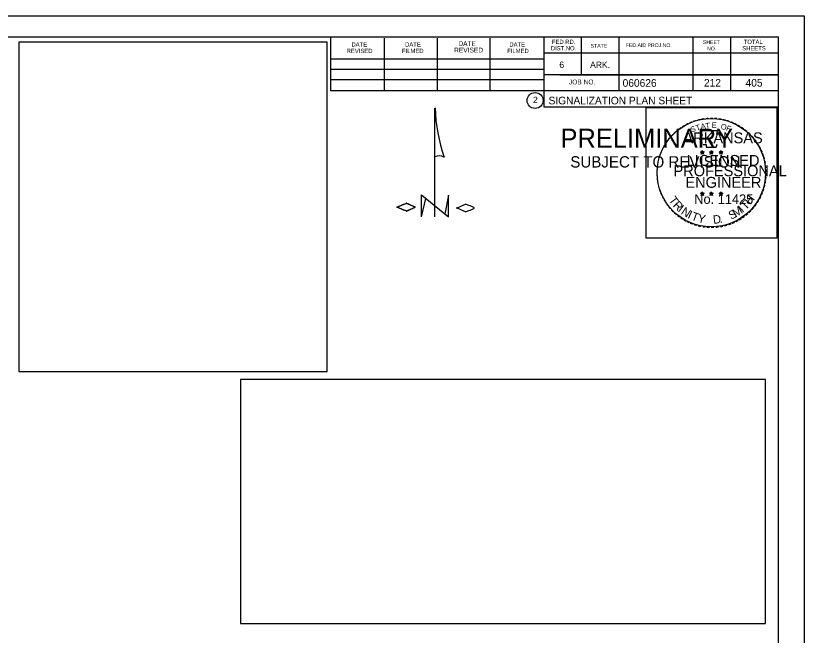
# Model space of a CAD drawing. Extents: x 1280742 to 1281742, y 1892348 to 1892988.
# Drawn here: x 1281307.2 to 1281741.9, y 1892646.8 to 1892988 of the extents above; entities that cross this region are included whole.
import ezdxf

# ---------------------------------------------------------------- set-up
doc = ezdxf.new("R2010")
doc.units = 0
for name, color, linetype in [('R_Border', 7, 'Continuous'), ('R_Border PE', 7, 'Continuous'), ('R_Border Prem', 7, 'Continuous'), ('R_No Plot', 7, 'Continuous'), ('T_Drafting', 7, 'Continuous')]:
    doc.layers.add(name, color=color, linetype=linetype)

msp = doc.modelspace()

# ---------------------------------------------------------------- linework, layer by layer
at = {"layer": 'R_Border'}
for p, q in [((1280779.11, 1892976.34), (1281727.65, 1892976.34)), ((1281480.87, 1892946.7), (1281480.87, 1892976.34)), ((1281510.45, 1892946.7), (1281510.45, 1892975.74)), ((1281539.73, 1892946.7), (1281539.73, 1892975.74)), ((1281568.77, 1892946.7), (1281568.77, 1892975.74)), ((1281598.35, 1892976.34), (1281598.35, 1892937.94)), ((1281618.87, 1892976.34), (1281618.87, 1892955.52)), ((1281639.69, 1892976.34), (1281639.69, 1892946.7)), ((1281680.43, 1892976.34), (1281680.43, 1892946.7)), ((1281701.25, 1892976.34), (1281701.25, 1892946.7)), ((1281727.65, 1892359.96), (1281727.65, 1892976.34)), ((1281480.87, 1892964.28), (1281598.35, 1892964.28)), ((1281727.65, 1892967.52), (1281598.35, 1892967.52)), ((1281727.65, 1892967.58), (1281727.65, 1892967.58)), ((1281480.87, 1892958.7), (1281598.35, 1892958.7)), ((1281727.65, 1892955.52), (1281598.35, 1892955.52)), ((1281607.23, 1892955.52), (1281727.65, 1892955.52)), ((1281480.87, 1892946.7), (1281480.87, 1892952.88)), ((1281480.87, 1892952.88), (1281598.35, 1892952.88)), ((1281727.65, 1892946.7), (1281480.87, 1892946.7)), ((1281598.35, 1892937.94), (1281727.65, 1892937.94))]:
    msp.add_line(p, q, dxfattribs=at)
msp.add_circle((1281593.51, 1892941.35), 4.4, dxfattribs=at)
at = {"layer": 'R_Border PE'}
for p, q in [((1281684.63, 1892913.02), (1281685.68, 1892912.69)), ((1281684.63, 1892913.02), (1281685.39, 1892912.89)), ((1281684.63, 1892913.02), (1281685.34, 1892912.66)), ((1281685.03, 1892911.8), (1281685.68, 1892912.69)), ((1281685.03, 1892911.8), (1281685.41, 1892912.53)), ((1281685.03, 1892911.8), (1281685.67, 1892912.45)), ((1281685.68, 1892913.78), (1281685.55, 1892913.03)), ((1281686.31, 1892911.8), (1281685.67, 1892912.44)), ((1281685.68, 1892912.69), (1281685.68, 1892913.78)), ((1281685.68, 1892913.78), (1281685.82, 1892913.03)), ((1281686.72, 1892913.02), (1281685.68, 1892912.69)), ((1281686.31, 1892911.8), (1281685.68, 1892912.69)), ((1281686.72, 1892913.02), (1281685.86, 1892912.87)), ((1281686.31, 1892911.8), (1281685.9, 1892912.67)), ((1281686.72, 1892913.02), (1281686.1, 1892912.72)), ((1281689.64, 1892913.02), (1281690.69, 1892912.69)), ((1281689.64, 1892913.02), (1281690.4, 1892912.89)), ((1281689.64, 1892913.02), (1281690.35, 1892912.66)), ((1281690.04, 1892911.8), (1281690.69, 1892912.69)), ((1281690.04, 1892911.8), (1281690.42, 1892912.53)), ((1281690.04, 1892911.8), (1281690.68, 1892912.45)), ((1281690.69, 1892913.78), (1281690.56, 1892913.03)), ((1281691.32, 1892911.8), (1281690.68, 1892912.44)), ((1281690.69, 1892912.69), (1281690.69, 1892913.78)), ((1281690.69, 1892913.78), (1281690.83, 1892913.03)), ((1281691.73, 1892913.02), (1281690.69, 1892912.69)), ((1281691.32, 1892911.8), (1281690.69, 1892912.69)), ((1281691.73, 1892913.02), (1281690.87, 1892912.87)), ((1281691.32, 1892911.8), (1281690.91, 1892912.67)), ((1281691.73, 1892913.02), (1281691.11, 1892912.72)), ((1281694.93, 1892912.99), (1281695.98, 1892912.65)), ((1281694.93, 1892912.99), (1281695.69, 1892912.85)), ((1281694.93, 1892912.99), (1281695.64, 1892912.62)), ((1281695.33, 1892911.76), (1281695.98, 1892912.65)), ((1281695.33, 1892911.76), (1281695.71, 1892912.49)), ((1281695.33, 1892911.76), (1281695.97, 1892912.41)), ((1281695.98, 1892913.75), (1281695.85, 1892912.99)), ((1281696.62, 1892911.76), (1281695.97, 1892912.4)), ((1281695.98, 1892912.65), (1281695.98, 1892913.75)), ((1281695.98, 1892913.75), (1281696.12, 1892913)), ((1281697.02, 1892912.99), (1281695.98, 1892912.65)), ((1281696.62, 1892911.76), (1281695.98, 1892912.65)), ((1281697.02, 1892912.99), (1281696.16, 1892912.84)), ((1281696.62, 1892911.76), (1281696.21, 1892912.63)), ((1281697.02, 1892912.99), (1281696.41, 1892912.68)), ((1281684.62, 1892890.3), (1281685.66, 1892889.97)), ((1281684.62, 1892890.3), (1281685.38, 1892890.17)), ((1281684.62, 1892890.3), (1281685.33, 1892889.94)), ((1281685.66, 1892891.06), (1281685.54, 1892890.31)), ((1281685.66, 1892889.97), (1281685.66, 1892891.06)), ((1281685.66, 1892891.06), (1281685.81, 1892890.31)), ((1281686.7, 1892890.3), (1281685.66, 1892889.97)), ((1281686.7, 1892890.3), (1281685.85, 1892890.16)), ((1281686.7, 1892890.3), (1281686.09, 1892890)), ((1281689.62, 1892890.3), (1281690.67, 1892889.97)), ((1281689.62, 1892890.3), (1281690.38, 1892890.17)), ((1281689.62, 1892890.3), (1281690.33, 1892889.94)), ((1281690.67, 1892891.06), (1281690.55, 1892890.31)), ((1281690.67, 1892889.97), (1281690.67, 1892891.06)), ((1281690.67, 1892891.06), (1281690.82, 1892890.31)), ((1281691.71, 1892890.3), (1281690.67, 1892889.97)), ((1281691.71, 1892890.3), (1281690.85, 1892890.16)), ((1281691.71, 1892890.3), (1281691.1, 1892890)), ((1281695.97, 1892891.03), (1281695.85, 1892890.28)), ((1281695.97, 1892889.94), (1281695.97, 1892891.03)), ((1281695.97, 1892891.03), (1281696.12, 1892890.28)), ((1281685.02, 1892889.08), (1281685.66, 1892889.97)), ((1281685.02, 1892889.08), (1281685.39, 1892889.81)), ((1281685.02, 1892889.08), (1281685.66, 1892889.73)), ((1281686.3, 1892889.08), (1281685.66, 1892889.97)), ((1281686.3, 1892889.08), (1281685.66, 1892889.72)), ((1281686.3, 1892889.08), (1281685.89, 1892889.95)), ((1281690.02, 1892889.08), (1281690.67, 1892889.97)), ((1281690.02, 1892889.08), (1281690.4, 1892889.81)), ((1281690.02, 1892889.08), (1281690.66, 1892889.73)), ((1281691.31, 1892889.08), (1281690.66, 1892889.72)), ((1281691.31, 1892889.08), (1281690.67, 1892889.97)), ((1281691.31, 1892889.08), (1281690.9, 1892889.95)), ((1281694.92, 1892890.27), (1281695.97, 1892889.94)), ((1281694.92, 1892890.27), (1281695.68, 1892890.14)), ((1281694.92, 1892890.27), (1281695.64, 1892889.91)), ((1281695.32, 1892889.05), (1281695.97, 1892889.94)), ((1281695.32, 1892889.05), (1281695.7, 1892889.78)), ((1281695.32, 1892889.05), (1281695.97, 1892889.7)), ((1281697.01, 1892890.27), (1281695.97, 1892889.94)), ((1281696.61, 1892889.05), (1281695.97, 1892889.94)), ((1281696.61, 1892889.05), (1281695.97, 1892889.69)), ((1281697.01, 1892890.27), (1281696.15, 1892890.13)), ((1281696.61, 1892889.05), (1281696.2, 1892889.92)), ((1281697.01, 1892890.27), (1281696.4, 1892889.97))]:
    msp.add_line(p, q, dxfattribs=at)
for points in [[(1281684.75, 1892924.66), (1281685.56, 1892922.17)], [(1281695.28, 1892921.89), (1281695.71, 1892922.74), (1281693.66, 1892922.67), (1281694.1, 1892924.66), (1281684.75, 1892924.66)], [(1281686.23, 1892917.39), (1281686.23, 1892917.13), (1281687.92, 1892917.07), (1281687.75, 1892915.65), (1281693.36, 1892915.65), (1281693.97, 1892917.26)], [(1281685.68, 1892913.78), (1281686.31, 1892911.8), (1281684.63, 1892913.02), (1281686.72, 1892913.02), (1281685.03, 1892911.8), (1281685.68, 1892913.78)], [(1281690.69, 1892913.78), (1281691.32, 1892911.8), (1281689.64, 1892913.02), (1281691.73, 1892913.02), (1281690.04, 1892911.8), (1281690.69, 1892913.78)], [(1281695.98, 1892913.75), (1281696.62, 1892911.76), (1281694.93, 1892912.99), (1281697.02, 1892912.99), (1281695.33, 1892911.76), (1281695.98, 1892913.75)], [(1281685.66, 1892891.06), (1281686.3, 1892889.08), (1281684.62, 1892890.3), (1281686.7, 1892890.3), (1281685.02, 1892889.08), (1281685.66, 1892891.06)], [(1281690.67, 1892891.06), (1281691.31, 1892889.08), (1281689.62, 1892890.3), (1281691.71, 1892890.3), (1281690.02, 1892889.08), (1281690.67, 1892891.06)], [(1281695.97, 1892891.03), (1281696.61, 1892889.05), (1281694.92, 1892890.27), (1281697.01, 1892890.27), (1281695.32, 1892889.05), (1281695.97, 1892891.03)]]:
    msp.add_lwpolyline(points, dxfattribs=at)
for centre, radius in [((1281685.67, 1892912.69), 0.517), ((1281685.67, 1892912.69), 0.434), ((1281685.67, 1892912.69), 0.347), ((1281685.67, 1892912.69), 0.297), ((1281685.67, 1892912.69), 0.224), ((1281685.67, 1892912.69), 0.149), ((1281685.67, 1892912.69), 0.0889), ((1281690.68, 1892912.69), 0.517), ((1281690.68, 1892912.69), 0.434), ((1281690.68, 1892912.69), 0.347), ((1281690.68, 1892912.69), 0.297), ((1281690.68, 1892912.69), 0.224), ((1281690.68, 1892912.69), 0.149), ((1281690.68, 1892912.69), 0.0889), ((1281695.97, 1892912.65), 0.517), ((1281695.97, 1892912.65), 0.434), ((1281695.97, 1892912.65), 0.347), ((1281695.97, 1892912.65), 0.297), ((1281695.97, 1892912.65), 0.224), ((1281695.97, 1892912.65), 0.149), ((1281695.97, 1892912.65), 0.0889), ((1281685.66, 1892889.97), 0.517), ((1281685.66, 1892889.97), 0.434), ((1281685.66, 1892889.97), 0.347), ((1281690.67, 1892889.97), 0.517), ((1281690.67, 1892889.97), 0.434), ((1281690.67, 1892889.97), 0.347), ((1281695.97, 1892889.94), 0.517), ((1281695.97, 1892889.94), 0.434), ((1281685.66, 1892889.97), 0.297), ((1281685.66, 1892889.97), 0.224), ((1281685.66, 1892889.97), 0.149), ((1281685.66, 1892889.97), 0.0889), ((1281690.67, 1892889.97), 0.297), ((1281690.67, 1892889.97), 0.224), ((1281690.67, 1892889.97), 0.149), ((1281690.67, 1892889.97), 0.0889), ((1281695.97, 1892889.94), 0.347), ((1281695.97, 1892889.94), 0.297), ((1281695.97, 1892889.94), 0.224), ((1281695.97, 1892889.94), 0.149), ((1281695.97, 1892889.94), 0.0889)]:
    msp.add_circle(centre, radius, dxfattribs=at)
at = {"layer": 'R_No Plot'}
for p, q in [((1280741.9, 1892988.02), (1281741.9, 1892988.02)), ((1281654.48, 1892868.89), (1281654.48, 1892868.89))]:
    msp.add_line(p, q, dxfattribs=at)
for points in [[(1280741.88, 1892988.02), (1281741.9, 1892988.02), (1281741.9, 1892348.01), (1280741.88, 1892348.01)], [(1281654.71, 1892937.57), (1281726.71, 1892937.57), (1281726.71, 1892865.57), (1281654.71, 1892865.57)]]:
    msp.add_lwpolyline(points, close=True, dxfattribs=at)
msp.add_circle((1281690.71, 1892901.57), 29.86, dxfattribs=at)
at = {"layer": 'T_Drafting'}
for p, q in [((1281538.3, 1892877.22), (1281538.3, 1892937.2)), ((1281530.79, 1892877.24), (1281533.26, 1892887.28)), ((1281530.8, 1892877.22), (1281530.8, 1892889.41)), ((1281530.8, 1892889.41), (1281545.79, 1892877.22)), ((1281545.79, 1892889.18), (1281543.66, 1892878.99)), ((1281545.79, 1892877.22), (1281545.79, 1892889.18)), ((1281545.79, 1892889.17), (1281545.79, 1892889.18))]:
    msp.add_line(p, q, dxfattribs=at)
for points in [[(1281308.78, 1892792.15), (1281478.92, 1892792.15), (1281478.92, 1892973.58), (1281308.78, 1892973.58)], [(1281431.13, 1892653.19), (1281720.63, 1892653.19), (1281720.63, 1892787.74), (1281431.13, 1892787.74)]]:
    msp.add_lwpolyline(points, close=True, dxfattribs=at)
for centre, radius, start, end in [((1281636.09, 1892941.13), 97.82, 182.2815, 198.4669), ((1281540.66, 1892905.27), 5.53, 61.6986, 115.682), ((1281452.74, 1893046.59), 176.2, 291.4742, 293.2539), ((1281452.74, 1892718.6), 176.2, 66.7461, 68.5258), ((1281452.97, 1893046.59), 176.2, 291.4742, 293.2539), ((1281452.97, 1892718.6), 176.2, 66.7461, 68.5258), ((1281494.06, 1892811.03), 78.93, 65.1071, 68.9839), ((1281494.06, 1892954.16), 78.93, 291.0161, 294.8929), ((1281494.29, 1892811.03), 78.93, 65.1071, 68.9839), ((1281494.29, 1892954.16), 78.93, 291.0161, 294.8929), ((1281485.6, 1893046.13), 176.2, 291.4742, 293.2539), ((1281485.6, 1892718.14), 176.2, 66.7461, 68.5258), ((1281526.91, 1892810.57), 78.93, 65.1071, 68.9839), ((1281526.91, 1892953.7), 78.93, 291.0161, 294.8929)]:
    msp.add_arc(centre, radius, start, end, dxfattribs=at)

# ---------------------------------------------------------------- texts
at = {"layer": 'R_Border'}
for s, height, p in [('DATE', 2.346, (1281492.27, 1892971.06)), ('DATE', 2.346, (1281521.85, 1892971.06)), ('DATE', 2.638, (1281551.19, 1892971.36)), ('DATE', 2.346, (1281579.33, 1892971.06)), ('FED.RD.', 2.346, (1281602.79, 1892972.5)), ('SHEET', 2.052, (1281686.01, 1892972.5)), ('TOTAL', 2.346, (1281708.57, 1892972.5)), ('REVISED', 2.346, (1281489.63, 1892967.52)), ('FILMED', 2.346, (1281520.11, 1892967.52)), ('REVISED', 2.638, (1281548.85, 1892967.82)), ('FILMED', 2.346, (1281578.13, 1892967.52)), ('DIST.NO.', 2.346, (1281602.19, 1892968.96)), ('STATE', 2.052, (1281624.15, 1892970.46)), ('FED.AID PROJ.NO.', 2.052, (1281643.53, 1892970.76)), ('NO.', 2.052, (1281688.35, 1892968.96)), ('SHEETS', 2.346, (1281707.73, 1892968.96)), ('6', 3.52, (1281606.87, 1892959.3)), ('ARK.', 3.517, (1281623.85, 1892959.3)), ('JOB NO.', 2.638, (1281612.15, 1892950.24)), ('060626', 4.2, (1281641.77, 1892948.92)), ('212', 4.2, (1281686.62, 1892949.01)), ('405', 4.2, (1281709.55, 1892949.01)), ('2', 3.52, (1281592.36, 1892939.89)), ('SIGNALIZATION PLAN SHEET', 4.2, (1281600.94, 1892939.23))]:
    msp.add_text(s, height=height, dxfattribs=at).set_placement(p)
at = {"layer": 'R_Border PE'}
for s, height, rotation, p in [('-', 4.8, 24.3072, (1281679.09, 1892927.23)), ('-', 4.8, 19.1761, (1281681, 1892928.04)), ('-', 4.8, 13.6302, (1281683.25, 1892928.76)), ('-', 4.8, 10.2193, (1281685.28, 1892929.25)), ('-', 4.8, 5.8968, (1281687.47, 1892929.58)), ('-', 4.8, 0.1862, (1281689.78, 1892929.79)), ('-', 4.8, 357.743, (1281691.95, 1892929.75)), ('-', 4.8, 352.1617, (1281694.18, 1892929.58)), ('-', 4.8, 347.2049, (1281696.34, 1892929.24)), ('-', 4.8, 342.3362, (1281698.25, 1892928.78)), ('-', 4.8, 337.8551, (1281700.45, 1892928.11)), ('-', 4.8, 38.9507, (1281672.24, 1892922.85)), ('-', 4.8, 36.2317, (1281673.67, 1892923.98)), ('-', 4.8, 34.0636, (1281675.4, 1892925.17)), ('-', 4.8, 28.7918, (1281677.19, 1892926.28)), ('S', 3, 21.594, (1281679.82, 1892923.69)), ('T', 3, 16.4036, (1281682.56, 1892924.68)), ('A', 3, 11.2132, (1281685.04, 1892925.44)), ('T', 3, 6.0228, (1281687.58, 1892925.93)), ('E', 3, 0.8323, (1281690.9, 1892926.26)), ('O', 3, 350.4515, (1281695.71, 1892925.63)), ('F', 3, 340.0707, (1281698.57, 1892924.95)), ('-', 4.8, 334.1211, (1281702.34, 1892927.3)), ('-', 4.8, 329.6409, (1281704.08, 1892926.45)), ('-', 4.8, 325.8627, (1281706.01, 1892925.36)), ('-', 4.8, 320.5297, (1281707.84, 1892924.09)), ('-', 4.8, 50.6142, (1281668.39, 1892918.71)), ('-', 4.8, 48.4231, (1281669.6, 1892920.16)), ('-', 4.8, 42.9622, (1281670.94, 1892921.6)), ('-', 4.8, 315.5786, (1281709.64, 1892922.62)), ('-', 4.8, 309.8797, (1281711.34, 1892920.97)), ('-', 4.8, 58.0706, (1281666.18, 1892915.42)), ('-', 4.8, 54.2325, (1281667.15, 1892917.01)), ('-', 4.8, 306.6522, (1281712.92, 1892919.17)), ('-', 4.2, 303.6753, (1281714.38, 1892917.46)), ('-', 4.8, 299.6684, (1281715.33, 1892915.64)), ('-', 4.8, 72.3945, (1281663.8, 1892909.86)), ('-', 4.8, 67.7743, (1281664.46, 1892911.75)), ('-', 4.8, 62.8713, (1281665.24, 1892913.58)), ('-', 4.8, 294.6628, (1281716.31, 1892913.8)), ('-', 4.8, 290.5728, (1281717.08, 1892912.07)), ('-', 4.8, 81.2013, (1281662.82, 1892905.58)), ('-', 4.8, 75.461, (1281663.21, 1892907.72)), ('-', 4.8, 285.1233, (1281717.78, 1892910.33)), ('-', 4.8, 280.5493, (1281718.38, 1892908.11)), ('-', 4.8, 85.1863, (1281662.59, 1892903.51)), ('-', 4.8, 276.5962, (1281718.86, 1892905.8)), ('-', 4.8, 274.3301, (1281719.04, 1892903.64)), ('-', 4.8, 94.1959, (1281662.62, 1892899.23)), ('-', 4.8, 89.0622, (1281662.51, 1892901.4)), ('-', 4.8, 263.5172, (1281719.09, 1892899.74)), ('-', 4.8, 269.9407, (1281719.15, 1892901.74)), ('-', 4.8, 98.9479, (1281662.83, 1892897.23)), ('-', 4.8, 101.7149, (1281663.24, 1892895.03)), ('-', 4.8, 255.7626, (1281718.55, 1892895.75)), ('-', 4.8, 260.9953, (1281718.88, 1892897.78)), ('-', 4.8, 105.4578, (1281663.72, 1892893.24)), ('-', 4.8, 109.0874, (1281664.37, 1892891.35)), ('-', 4.8, 114.0643, (1281665.13, 1892889.56)), ('-', 4.8, 247.8887, (1281717.33, 1892891.57)), ('-', 4.8, 252.8681, (1281718, 1892893.59)), ('-', 4.8, 115.7289, (1281666.05, 1892887.71)), ('-', 4.8, 120.4471, (1281667.12, 1892885.95)), ('T', 4.62, 306.0406, (1281666.94, 1892886.48)), ('R', 4.62, 314.005, (1281669.23, 1892883.34)), ('T', 4.62, 46.6444, (1281709.63, 1892880.76)), ('H', 4.62, 54.6088, (1281712.3, 1892883.59)), ('-', 4.8, 239.0712, (1281715.37, 1892887.43)), ('-', 4.8, 244.6197, (1281716.55, 1892889.68)), ('-', 4.8, 125.8934, (1281668.33, 1892884.27)), ('-', 4.8, 130.7181, (1281669.71, 1892882.61)), ('I', 4.62, 321.9694, (1281671.93, 1892880.54)), ('N', 4.62, 326.5002, (1281673.63, 1892879.13)), ('M', 4.62, 32.6563, (1281704.1, 1892876.79)), ('I', 4.62, 42.1136, (1281707.95, 1892879.33)), ('-', 4.8, 231.2538, (1281712.87, 1892883.77)), ('-', 4.8, 233.8452, (1281714.16, 1892885.47)), ('-', 4.8, 134.2238, (1281671.26, 1892880.98)), ('-', 4.8, 138.9338, (1281672.84, 1892879.58)), ('-', 4.8, 144.6463, (1281674.51, 1892878.37)), ('I', 4.62, 335.3603, (1281677.26, 1892876.77)), ('T', 4.62, 339.8912, (1281679.24, 1892875.79)), ('Y', 4.62, 347.8556, (1281682.89, 1892874.45)), ('D', 4.62, 6.3969, (1281691.85, 1892873.38)), ('S', 4.62, 26.9312, (1281701.58, 1892875.57)), ('-', 4.8, 215.7363, (1281708.22, 1892879.13)), ('-', 4.8, 221.0851, (1281709.87, 1892880.55)), ('-', 4.8, 225.7653, (1281711.43, 1892882.08)), ('-', 4.8, 148.0898, (1281676.19, 1892877.25)), ('-', 4.8, 151.5704, (1281677.93, 1892876.28)), ('-', 4.8, 154.6002, (1281679.49, 1892875.54)), ('-', 4.8, 158.5612, (1281681.36, 1892874.77)), ('-', 4.8, 162.7983, (1281683.43, 1892874.14)), ('.', 4.62, 13.7642, (1281695.42, 1892873.76)), ('-', 4.8, 200.7184, (1281701.22, 1892875.16)), ('-', 4.8, 204.2516, (1281703.07, 1892875.98)), ('-', 4.8, 207.3568, (1281704.94, 1892876.93)), ('-', 4.8, 212.2491, (1281706.62, 1892877.97)), ('-', 4.8, 167.5555, (1281685.57, 1892873.64)), ('-', 4.8, 173.1155, (1281687.89, 1892873.31)), ('-', 4.8, 176.5183, (1281690.13, 1892873.15)), ('-', 4.8, 181.5918, (1281692.36, 1892873.21)), ('-', 4.8, 185.8167, (1281694.79, 1892873.44)), ('-', 4.8, 191.2858, (1281697, 1892873.84)), ('-', 4.8, 195.4743, (1281699.18, 1892874.43))]:
    msp.add_text(s, height=height, rotation=rotation, dxfattribs=at).set_placement(p)
for s, height, p in [('ARKANSAS', 6, (1281675.31, 1892917.79)), ('DWB', 0.03, (1281685.64, 1892912.67)), ('DWB', 0.03, (1281690.65, 1892912.67)), ('DWB', 0.03, (1281695.94, 1892912.64)), ('LICENSED', 6, (1281677.1, 1892905.34)), ('PROFESSIONAL', 6, (1281669.83, 1892899.63)), ('ENGINEER', 6, (1281676.39, 1892893.26)), ('No. 11425', 5.271, (1281681.28, 1892884.4)), ('DWB', 0.03, (1281685.63, 1892889.95)), ('DWB', 0.03, (1281690.63, 1892889.95)), ('DWB', 0.03, (1281695.93, 1892889.92))]:
    msp.add_text(s, height=height, dxfattribs=at).set_placement(p)
at = {"layer": 'R_Border Prem'}
for s, height, p in [('PRELIMINARY', 10.5, (1281607.5, 1892915.33)), ('SUBJECT TO REVISION', 6.2253, (1281612.93, 1892904.44))]:
    msp.add_text(s, height=height, dxfattribs=at).set_placement(p)

doc.saveas('drawing.dxf')
